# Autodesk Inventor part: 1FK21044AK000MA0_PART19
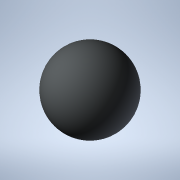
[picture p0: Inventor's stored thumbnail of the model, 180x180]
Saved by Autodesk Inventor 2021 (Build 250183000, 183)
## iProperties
Created: 2025-04
Part Number: 1FK21044AK000MA0_PART19
Material: Generic
Catalog Web Link: www.3dfindit.com
Description: -Servo synchronous motor
Document SubType Name: Modeling
Designer: psAdmin
Mass: 0.137258 g
Surface Area: 1.2868 cm^2
Volume: 0.137258 cm^3
Density: 1 g/cm^3
Appearance: PSOLRGB-212-217-219
Category: PARTsolutions
Title: 1FK21044AK000MA0_PART19
Author: Cadenas PARTsolutions
Comments: Servo synchronous motor
Sending System: PARTsolutions
Preprocessor: ST-DEVELOPER v19.3
PSOL_IDENT_0: {$CADENAS_DATA/23d-libs/siemens_ag/_cat_/87/f4/1fk21044ak000ma0.prj},216 {VTYP=3D},{NB=1FK21044AK000
PSOL_IDENT_1: MA0_PART19},{LINA=1FK21044AK000MA0_PART19},{NN=1FK21044AK000MA0_PART19},{NOPRJ=TRUE},{DATE=19.08.202
PSOL_IDENT_2: 5 14:00:48},{GEOMDATE=30.07.2025 02:00:50},{VERSION=},{LINEID=10},{WBVAR=},{WBNUMERIC=}  {NB=1FK2104
PSOL_IDENT_3: 4AK000MA0_PART19},{LINA=1FK21044AK000MA0_PART19},{KT=DUMMY},{PREVIEW=../../../_pool_/cb/72/p_d211_xx
PSOL_IDENT_4: _00434j.png},{DESCSHORT=SIMOTICS S-1FK2 HD, SINAMICS S210 3AC 400V-480V, 0.95 Nm, 6000 rpm},{DESCLON
PSOL_IDENT_5: G=SIMOTICS S-1FK2 HD servo motor M0=1.27 Nm; PN = 0.6 kW at nN=6000 rpm (380-480 V); PN = 0.4 kW at
PSOL_IDENT_6: nN=3000 rpm (200-240 V); degree of protection IP64; cylindrical shaft D19x40mm; absolute encoder 22-
PSOL_IDENT_7: bit + 12-bit multiturn (encoder AM22DQC); with OCC interface; plug size M17, rotatable; SIMOTICS S-1
PSOL_IDENT_8: FK2 servomotorfor a wide range of uses in industrial environments. SIMOTICS S‑1FK2 servomotors are c
PSOL_IDENT_9: ompact synchronous motors with a high dynamic performance that set themselves apart as a result of t
PSOL_IDENT_10: heir high power density, degree of protection and overload capability. The motors are available in t
PSOL_IDENT_11: wo variants: as High Dynamic variant (highest dynamic performance as a result of the low intrinsic m
PSOL_IDENT_12: oment of inertia for applications demanding a high dynamic performance with low moved masses) - and
PSOL_IDENT_13: as Compact variant (precise and stable closed-loop control for medium up to large moved masses as a
PSOL_IDENT_14: result of a medium intrinsic moment of inertia). SIMOTICSS‑1FK2 servomotors fully exploit their stre
PSOL_IDENT_15: ngths in a system with the SINAMICSS210 frequency converter and simple connection using the one cabl
PSOL_IDENT_16: e connection (OCC). Advantages include the short control and positioning times, fast and precise cor
PSOL_IDENT_17: rection of disturbing quantities as well as stable control with a high dynamic performance. The serv
PSOL_IDENT_18: o motors can be configured to address a wide range of requirements. For example with and without hol
PSOL_IDENT_19: ding brake, IP64 or IP65 degree of protection, singleturn or multiturn absolute encoders - to name j
PSOL_IDENT_20: ust a few. Further, the servomotors are available in different shaft heights extending from 20 to 10
PSOL_IDENT_21: 0. A shaft sealing ring is available to achieve an IP65 degree of protection and for subsequent moun
PSOL_IDENT_22: ting at the motor or as spare part. SIMOTICS - the optimum motor for each and every motion control a
PSOL_IDENT_23: pplication.},{INTNO=195125056312},{SUPPLIERALTNO=1FK2104-4AK00-0MA0},{MANUID=1FK21044AK000MA0},{MANU
PSOL_IDENT_24: NAME=Siemens},{MANUTYPEDESC=Synchronous motor 1FK2-HD 1,27 Nm},{AAU732=SIMOTICS},{AAO057=S-1FK2},{AA
PSOL_IDENT_25: U734=SIMOTICS S-1FK2 HD servo motor M0=1.27 Nm; PN = 0.6 kW at nN=6000 rpm (380-480 V); PN = 0.4 kW
PSOL_IDENT_26: at nN=3000 rpm (200-240 V); degree of protection IP64; cylindrical shaft D19x40mm; absolute encoder
PSOL_IDENT_27: 22-bit + 12-bit multiturn (encoder AM22DQC); with OCC interface; plug size M17, rotatable;},{AAW338=
PSOL_IDENT_28: Synchronous motor 1FK2-HD 1,27 Nm},{AAO742=SIMOTICS},{AAO663=4042948690994},{NOCUPEROU=1},{PRICEQUAN
PSOL_IDENT_29: TITY=1},{QUANTITYMIN=1},{QUANTITYINT=1},{CTN=85015100},{COO=DE},{AAO676=1FK2104-4AK00-0MA0},{AAO677=
PSOL_IDENT_30: Siemens AG},{ORDERUNIT=C62},{CONTENTUNIT=C62}
NB: 1FK21044AK000MA0_PART19
NT: Servo synchronous motor
NBSYN: $MANUID._PART19
LINA: 1FK21044AK000MA0_PART19
CATALOG: SIEMENS
PREVIEW: ../../../_pool_/cb/72/p_d211_xx_00434j.png
DESCSHORT: SIMOTICS S-1FK2 HD, SINAMICS S210 3AC 400V-480V, 0.95 Nm, 6000 rpm
DESCLONG: SIMOTICS S-1FK2 HD servo motor M0=1.27 Nm; PN = 0.6 kW at nN=6000 rpm (380-480 V); PN = 0.4 kW at nN=3000 rpm (200-240 V); degree of protection IP64; cylindrica
INTNO: 195125056312
SUPPLIERALTNO: 1FK2104-4AK00-0MA0
MANUID: 1FK21044AK000MA0
MANUNAME: Siemens
MANUTYPEDESC: Synchronous motor 1FK2-HD 1,27 Nm
AAU732: SIMOTICS
AAO057: S-1FK2
AAU734: SIMOTICS S-1FK2 HD servo motor M0=1.27 Nm; PN = 0.6 kW at nN=6000 rpm (380-480 V); PN = 0.4 kW at nN=3000 rpm (200-240 V); degree of protection IP64; cylindrica
AAW338: Synchronous motor 1FK2-HD 1,27 Nm
AAO742: SIMOTICS
AAO663: 4042948690994.0
NOCUPEROU: 1
PRICEQUANTITY: 1
QUANTITYMIN: 1
QUANTITYINT: 1
CTN: 85015100
COO: DE
ARTICLENO: 1FK21044AK000MA0_PART19
BOMINFO: 1FK21044AK000MA0_PART19
CREATOR: CADENAS GmbH
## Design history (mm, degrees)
feature "2025_04_17_15_37_40_0588"
body "Solid1"
